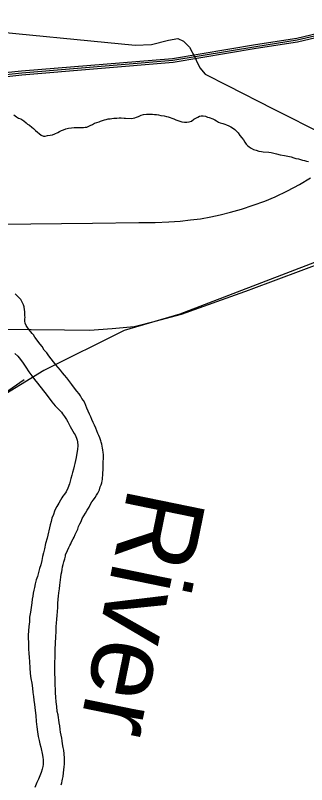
# Model space of a CAD drawing. Extents: x 0 to 34, y 0 to 22.
# Drawn here: x 6.286 to 6.635, y 14.261 to 15.185 of the extents above; entities that cross this region are included whole.
import ezdxf

# ---------------------------------------------------------------- set-up
doc = ezdxf.new("R2010")
doc.units = 0
for name, color, linetype in [('GM_X_City_Street', 7, 'Continuous'), ('GM_X_County_Road', 7, 'Continuous'), ('GM_X_Major_River', 7, 'Continuous'), ('GM_X_Major_River_Text', 7, 'Continuous'), ('GM_X_Minor_River', 7, 'Continuous'), ('GM_X_Rail_Line', 7, 'Continuous'), ('GM_X_US_Route', 7, 'Continuous')]:
    doc.layers.add(name, color=color, linetype=linetype)

msp = doc.modelspace()

# ---------------------------------------------------------------- linework, layer by layer
at = {"layer": 'GM_X_City_Street'}
msp.add_lwpolyline([(6.21041, 14.69084), (6.22755, 14.70042), (6.29603, 14.74753)], dxfattribs=at)
at = {"layer": 'GM_X_County_Road'}
msp.add_line((6.59494, 15.07279), (6.72075, 15.00881), dxfattribs=at)
for points in [[(6.20507, 15.17118), (6.20839, 15.16993), (6.23252, 15.16834), (6.42938, 15.14894), (6.44878, 15.14989), (6.46913, 15.15509), (6.48049, 15.15698), (6.48712, 15.15367), (6.49469, 15.14657), (6.50131, 15.1338), (6.50262, 15.13107)], [(6.50262, 15.13107), (6.50699, 15.12197), (6.51314, 15.11439), (6.54012, 15.10067), (6.59494, 15.07279)]]:
    msp.add_lwpolyline(points, dxfattribs=at)
at = {"layer": 'GM_X_Major_River'}
for points in [[(6.29681, 14.81782), (6.29679, 14.8201), (6.29714, 14.82239), (6.29712, 14.82429), (6.2971, 14.82619), (6.29706, 14.82923), (6.29666, 14.83151), (6.29624, 14.83493), (6.29546, 14.8372), (6.2939, 14.84061), (6.29197, 14.84363), (6.28928, 14.84665), (6.28736, 14.84853), (6.28544, 14.85042)], [(6.33873, 14.50066), (6.34013, 14.51057), (6.34047, 14.51399), (6.3412, 14.51666), (6.34155, 14.51971), (6.34227, 14.52276), (6.343, 14.52581), (6.34372, 14.52886), (6.34482, 14.53229), (6.34554, 14.53572), (6.3459, 14.53763), (6.34739, 14.5403), (6.34812, 14.54259), (6.3496, 14.54603), (6.35109, 14.54833), (6.35221, 14.55062), (6.35294, 14.55291), (6.3548, 14.55635), (6.35592, 14.55827), (6.3574, 14.5617), (6.35888, 14.56476), (6.36036, 14.5682), (6.36146, 14.57125), (6.36295, 14.57431), (6.36443, 14.57737), (6.36591, 14.5808), (6.36777, 14.58425), (6.36963, 14.58731), (6.37187, 14.59075), (6.37411, 14.59458), (6.37559, 14.59802), (6.37745, 14.6007), (6.37932, 14.60338), (6.38119, 14.60606), (6.38306, 14.60874), (6.38454, 14.61141), (6.3864, 14.61524), (6.3875, 14.61867), (6.38861, 14.62134), (6.38934, 14.62363), (6.38969, 14.62592), (6.39005, 14.62783), (6.39003, 14.63011), (6.39038, 14.63239), (6.39103, 14.64229), (6.39099, 14.64533), (6.39095, 14.64951), (6.3913, 14.65218), (6.39127, 14.65484), (6.39124, 14.6575), (6.39083, 14.66016), (6.39041, 14.6632), (6.39001, 14.66548), (6.3896, 14.66775), (6.3892, 14.67003), (6.38841, 14.67231), (6.38801, 14.6742), (6.38683, 14.67762), (6.38566, 14.68065), (6.3845, 14.68292), (6.38332, 14.68595), (6.38215, 14.68936), (6.38059, 14.69277), (6.37903, 14.69617), (6.37748, 14.69958), (6.37592, 14.70299), (6.37437, 14.70602), (6.37281, 14.7098), (6.37125, 14.71321), (6.37007, 14.71662), (6.3689, 14.71965), (6.36735, 14.7223), (6.36542, 14.72494), (6.36387, 14.72797), (6.36194, 14.73061), (6.35925, 14.73363), (6.35655, 14.73741), (6.35347, 14.74156), (6.34962, 14.74646), (6.3473, 14.74986), (6.34461, 14.75288), (6.34192, 14.7559), (6.33961, 14.75891), (6.33692, 14.76193), (6.33422, 14.76533), (6.33114, 14.7691), (6.32845, 14.7725), (6.32575, 14.77627), (6.32343, 14.77967), (6.31998, 14.78306), (6.31766, 14.78722), (6.31534, 14.79024), (6.3088, 14.79854), (6.30725, 14.80119), (6.30571, 14.80308), (6.30417, 14.80496), (6.30263, 14.80685), (6.29994, 14.81024), (6.29839, 14.81251), (6.29722, 14.81516), (6.29681, 14.81782)], [(6.28511, 14.77891), (6.28856, 14.77552), (6.29164, 14.77175), (6.29473, 14.76722), (6.2982, 14.76231), (6.30167, 14.75702), (6.30514, 14.75211), (6.30861, 14.74758), (6.31208, 14.74343), (6.32363, 14.72833), (6.32941, 14.72078), (6.33326, 14.71625), (6.33633, 14.71286), (6.33825, 14.71136), (6.34094, 14.70835), (6.3421, 14.70645), (6.34441, 14.70344), (6.34673, 14.69966), (6.34866, 14.69701), (6.34983, 14.69436), (6.35138, 14.69134), (6.35293, 14.68831), (6.35448, 14.68566), (6.35603, 14.68301), (6.35719, 14.68112), (6.35797, 14.67923), (6.35875, 14.67734), (6.35953, 14.67506), (6.35994, 14.67278), (6.36036, 14.6686), (6.36004, 14.66366), (6.35933, 14.65909), (6.35863, 14.65413), (6.35753, 14.65032), (6.35681, 14.64689), (6.35609, 14.64384), (6.35537, 14.64003), (6.35428, 14.63622), (6.35318, 14.63278), (6.35208, 14.62897), (6.35064, 14.62249), (6.34842, 14.61714), (6.34657, 14.61294), (6.34433, 14.60987), (6.34246, 14.60757), (6.34134, 14.60566), (6.33985, 14.60298), (6.33762, 14.59916), (6.33538, 14.59533), (6.33389, 14.59266), (6.33241, 14.5896), (6.33131, 14.58578), (6.32947, 14.5812), (6.32837, 14.57739), (6.32728, 14.57319), (6.32367, 14.55718), (6.32184, 14.5507), (6.32039, 14.5446), (6.31931, 14.53964), (6.31822, 14.53507), (6.31713, 14.53049), (6.31606, 14.52516), (6.31458, 14.52096), (6.3135, 14.51601), (6.31203, 14.51143), (6.31056, 14.50723), (6.30948, 14.50228), (6.30839, 14.49808), (6.30767, 14.49465), (6.30695, 14.49122), (6.30661, 14.48779), (6.30589, 14.48398), (6.30518, 14.47979)], [(6.34067, 14.26108), (6.3414, 14.26375), (6.34175, 14.26603), (6.34211, 14.26794), (6.34283, 14.27099), (6.34316, 14.27556), (6.34388, 14.27937), (6.34422, 14.28279), (6.34456, 14.28584), (6.34453, 14.2885), (6.34451, 14.29078), (6.34448, 14.29344), (6.34361, 14.30294), (6.34282, 14.30598), (6.34201, 14.31053), (6.34159, 14.31395), (6.34117, 14.31699), (6.34037, 14.32079), (6.33958, 14.3242), (6.33916, 14.32762), (6.33873, 14.3318), (6.33831, 14.3356), (6.33789, 14.33902), (6.33748, 14.34168), (6.33706, 14.34509), (6.33588, 14.34927), (6.33543, 14.35535), (6.33461, 14.36066), (6.33417, 14.36637), (6.33373, 14.37168), (6.33368, 14.37625), (6.33325, 14.38043), (6.33321, 14.38385), (6.33317, 14.38727), (6.33314, 14.39031), (6.3331, 14.39336), (6.33306, 14.39678), (6.33302, 14.40096), (6.33297, 14.40477), (6.33293, 14.40895), (6.33326, 14.41352), (6.33321, 14.4177), (6.33317, 14.4215), (6.3335, 14.42531), (6.33383, 14.4295), (6.33379, 14.4333), (6.33413, 14.43673), (6.33409, 14.44053), (6.33443, 14.44357), (6.33439, 14.44776), (6.33435, 14.45118), (6.33506, 14.45537), (6.33539, 14.45994), (6.33572, 14.4645), (6.33605, 14.46907), (6.33637, 14.47402), (6.33669, 14.47897), (6.33702, 14.48391), (6.33735, 14.48772), (6.33769, 14.49153), (6.33839, 14.49648), (6.33873, 14.50066)], [(6.30518, 14.47979), (6.30449, 14.47408), (6.30379, 14.46837), (6.30272, 14.46227), (6.3024, 14.45695), (6.30171, 14.45123), (6.30138, 14.44591), (6.30106, 14.44096), (6.30111, 14.43677), (6.30116, 14.43259), (6.3012, 14.42879), (6.30125, 14.42461), (6.30169, 14.41891), (6.30212, 14.41435), (6.30256, 14.40865), (6.30302, 14.4018), (6.30348, 14.39496), (6.30431, 14.38889), (6.30513, 14.38319), (6.30596, 14.37711), (6.30639, 14.37217), (6.30721, 14.36724), (6.30764, 14.36268), (6.30845, 14.35774), (6.30929, 14.35052), (6.31012, 14.34445), (6.31058, 14.33723), (6.31141, 14.33077), (6.31224, 14.32469), (6.31306, 14.31937), (6.31425, 14.31444), (6.31506, 14.31027), (6.31624, 14.30648), (6.31825, 14.29661), (6.31866, 14.29395), (6.31907, 14.29167), (6.31909, 14.28977), (6.31911, 14.28787), (6.31875, 14.28558), (6.3184, 14.2833), (6.31768, 14.27987), (6.31659, 14.27605), (6.31511, 14.27185), (6.31326, 14.26803), (6.31141, 14.26383), (6.30882, 14.2581)]]:
    msp.add_lwpolyline(points, dxfattribs=at)
at = {"layer": 'GM_X_Minor_River'}
for points in [[(6.28378, 15.06528), (6.28684, 15.06303), (6.28951, 15.06154), (6.29218, 15.06042), (6.29562, 15.05818), (6.29868, 15.05592), (6.30022, 15.05404), (6.30251, 15.05292), (6.3052, 15.05066), (6.30749, 15.04879), (6.3098, 15.04652), (6.3167, 15.04089), (6.31936, 15.03978), (6.32126, 15.03979), (6.32429, 15.04059), (6.32732, 15.04099), (6.32997, 15.0414), (6.333, 15.04257), (6.3364, 15.04413), (6.33866, 15.04529), (6.34092, 15.04645), (6.34319, 15.04724), (6.34622, 15.04841), (6.34924, 15.0492), (6.35303, 15.04962), (6.35607, 15.05003), (6.35796, 15.05005), (6.36062, 15.05007), (6.36366, 15.05011), (6.36745, 15.05014), (6.36935, 15.05054), (6.37124, 15.05056), (6.3754, 15.0525), (6.37804, 15.05367), (6.38068, 15.05522), (6.38332, 15.05638), (6.38597, 15.05717), (6.38786, 15.05795), (6.39013, 15.05873), (6.3924, 15.05952), (6.39467, 15.05992), (6.39694, 15.0607), (6.39922, 15.06073), (6.40149, 15.06113), (6.40376, 15.06153), (6.40718, 15.06157), (6.41021, 15.0616), (6.41249, 15.06162), (6.41591, 15.06127), (6.41781, 15.06129), (6.42464, 15.06098), (6.42692, 15.06138)], [(6.42692, 15.06138), (6.42881, 15.06178), (6.43108, 15.06257), (6.43335, 15.06335), (6.43637, 15.0649), (6.43939, 15.06569), (6.44281, 15.0661), (6.44508, 15.06613), (6.44774, 15.06615), (6.45002, 15.06618), (6.45268, 15.06582), (6.45496, 15.06585), (6.45724, 15.06549), (6.46028, 15.06476), (6.46409, 15.06403), (6.46675, 15.0633), (6.46903, 15.06294), (6.47132, 15.0622), (6.47322, 15.06146), (6.47551, 15.06073), (6.47818, 15.05923), (6.48161, 15.05812), (6.48542, 15.05702), (6.48846, 15.05667), (6.49112, 15.0567), (6.49415, 15.05711), (6.4968, 15.05789), (6.49981, 15.06021), (6.50207, 15.06137), (6.50434, 15.06253), (6.5066, 15.0637), (6.50849, 15.06409), (6.51077, 15.06412), (6.51381, 15.06377), (6.5161, 15.06265), (6.518, 15.06229), (6.52258, 15.06043), (6.52487, 15.05932), (6.52678, 15.05819), (6.52945, 15.0567), (6.53136, 15.05596), (6.53441, 15.05484), (6.53707, 15.05411), (6.53898, 15.05337), (6.54165, 15.05226), (6.54394, 15.05114), (6.54624, 15.04964), (6.54891, 15.04776), (6.55083, 15.04588), (6.55276, 15.04362), (6.55507, 15.0406), (6.55737, 15.03796), (6.5593, 15.03532), (6.56085, 15.03267), (6.5624, 15.03002), (6.56432, 15.02814), (6.56623, 15.02702), (6.56852, 15.02552), (6.5712, 15.02364), (6.57463, 15.02292), (6.57767, 15.02181), (6.58071, 15.02146), (6.58299, 15.0211), (6.58984, 15.02041), (6.5925, 15.02005), (6.59554, 15.01932), (6.59897, 15.0186), (6.60315, 15.0175), (6.60848, 15.01641), (6.61266, 15.01569), (6.61647, 15.01497), (6.61952, 15.01386), (6.62218, 15.01312), (6.62522, 15.01239), (6.62751, 15.01165), (6.63018, 15.01092), (6.63246, 15.01056), (6.63474, 15.00982), (6.6374, 15.00947)]]:
    msp.add_lwpolyline(points, dxfattribs=at)
at = {"layer": 'GM_X_Rail_Line'}
for points in [[(8.90008, 16.27609), (8.28464, 16.05251), (8.2351, 16.03075), (7.62857, 15.55854), (7.35221, 15.32854), (6.98093, 15.0864), (6.94685, 15.07059), (6.85677, 15.01096), (6.78007, 14.94768), (6.74233, 14.92578), (6.48307, 14.82604), (6.41613, 14.80659), (6.31973, 14.75852), (6.2075, 14.68975), (6.18014, 14.67712), (6.14998, 14.67432), (6.11427, 14.67643), (6.10573, 14.62409), (6.06796, 14.54131), (6.04876, 14.50294)], [(5.59634, 14.8185), (5.69011, 14.88155), (5.76614, 14.93325), (5.82475, 14.97463), (5.84875, 14.99074), (5.86984, 15.00332), (5.90414, 15.02306), (5.92782, 15.03494), (5.95169, 15.04645), (5.98, 15.05746), (6.0153, 15.07096), (6.04989, 15.08205), (6.0869, 15.09151), (6.11042, 15.09739), (6.14015, 15.10246), (6.29309, 15.11804), (6.47415, 15.1332), (6.57359, 15.14982), (6.62328, 15.15755), (6.67368, 15.16941)], [(5.59767, 14.8166), (5.70921, 14.89025), (5.78156, 14.94135), (5.82643, 14.97262), (5.8574, 14.99287), (5.89153, 15.01187), (5.91997, 15.02767), (5.93943, 15.03747), (5.96828, 15.04978), (5.99732, 15.06099), (6.03393, 15.07357), (6.06817, 15.08264), (6.10222, 15.0928), (6.14387, 15.10011), (6.29329, 15.11573), (6.47444, 15.13089), (6.57396, 15.14753), (6.62373, 15.15527), (6.67426, 15.16717)], [(5.60099, 14.81166), (5.71201, 14.88844), (5.78802, 14.94161), (5.8296, 14.97045), (5.84645, 14.98207), (5.86681, 14.99427), (5.89267, 15.00912), (5.92039, 15.02344), (5.95639, 15.0397), (5.98321, 15.0518), (6.01612, 15.06416), (6.0682, 15.07988), (6.10318, 15.08968), (6.1369, 15.09616), (6.29348, 15.11342), (6.47473, 15.12859), (6.57433, 15.14525), (6.62418, 15.15299), (6.67484, 15.16492)], [(6.11803, 14.9325), (6.37803, 14.93534), (6.4338, 14.93596), (6.45342, 14.93633), (6.46975, 14.93704), (6.48345, 14.93793), (6.49571, 14.93922), (6.50756, 14.94075), (6.51997, 14.94293), (6.5311, 14.94542), (6.54376, 14.94841), (6.55705, 14.95234), (6.57093, 14.95687), (6.5848, 14.96195), (6.59721, 14.96711), (6.61192, 14.97401), (6.62656, 14.98195), (6.63962, 14.98961)]]:
    msp.add_lwpolyline(points, dxfattribs=at)
at = {"layer": 'GM_X_US_Route'}
for p, q in [((6.53832, 14.84544), (6.56645, 14.85552)), ((6.11649, 14.80997), (6.3446, 14.80741))]:
    msp.add_line(p, q, dxfattribs=at)
for points in [[(6.56645, 14.85552), (6.56832, 14.85619), (6.71845, 14.91226), (6.74259, 14.92203), (6.75868, 14.93065), (6.86298, 15.00565), (6.89281, 15.02833), (6.94783, 15.06458), (6.9967, 15.09629), (7.00443, 15.1011)], [(6.3446, 14.80741), (6.37436, 14.80707), (6.40187, 14.80891), (6.42809, 14.8115), (6.45495, 14.8183), (6.48487, 14.82628), (6.53832, 14.84544)]]:
    msp.add_lwpolyline(points, dxfattribs=at)

# ---------------------------------------------------------------- texts
at = {"layer": 'GM_X_Major_River_Text'}
msp.add_text('River', height=0.09475, rotation=258.42055, dxfattribs=at).set_placement((6.42186, 14.62095))

doc.saveas('drawing.dxf')
